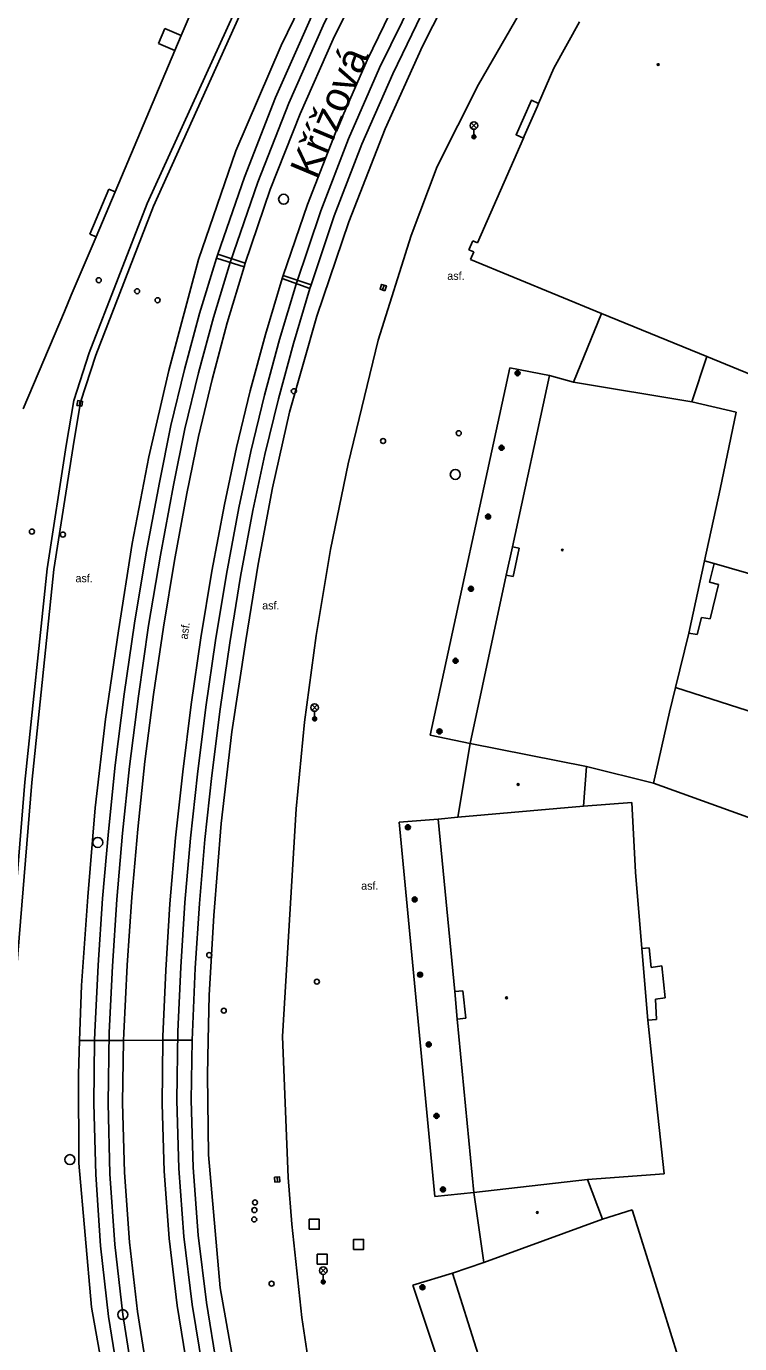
# Model space of a CAD drawing. Extents: x -599770 to -598493, y -1162076 to -1159209.
# Drawn here: x -599258.8 to -599223.2, y -1161450.6 to -1161384.7 of the extents above; entities that cross this region are included whole.
import ezdxf

# ---------------------------------------------------------------- set-up
doc = ezdxf.new("R2010")
doc.units = 0
doc.layers.add('Podklad', color=7, linetype='Continuous')

msp = doc.modelspace()

# ---------------------------------------------------------------- linework, layer by layer
at = {"layer": 'Podklad'}
for p, q in [((-599236.582, -1161389.83), (-599236.317, -1161389.565)), ((-599236.582, -1161389.565), (-599236.317, -1161389.83)), ((-599236.45, -1161389.885), (-599236.45, -1161390.26)), ((-599241.017, -1161397.919), (-599240.943, -1161397.681)), ((-599256.171, -1161403.713), (-599256.129, -1161403.467)), ((-599244.542, -1161418.93), (-599244.277, -1161418.665)), ((-599244.542, -1161418.665), (-599244.277, -1161418.93)), ((-599244.41, -1161418.985), (-599244.41, -1161419.36)), ((-599246.286, -1161442.265), (-599246.274, -1161442.515)), ((-599244.113, -1161447.08), (-599243.848, -1161446.815)), ((-599244.113, -1161446.815), (-599243.848, -1161447.08)), ((-599243.98, -1161447.135), (-599243.98, -1161447.51))]:
    msp.add_line(p, q, dxfattribs=at)
for points in [[(-599260.26, -1161446.97), (-599259.67, -1161436.44), (-599258.54, -1161422.55), (-599257.44, -1161411.89), (-599256.48, -1161405.74), (-599256.11, -1161403.52), (-599255.35, -1161401.18), (-599252.46, -1161393.72), (-599243.35, -1161373.53), (-599229.69, -1161346.19), (-599226.26, -1161338.15), (-599225.07, -1161333.53), (-599224.41, -1161329.22), (-599224.11, -1161321.1), (-599224.34, -1161312.95), (-599224.48, -1161311.25), (-599225.01, -1161307.91), (-599239.94, -1161263.56), (-599245.55, -1161247.67)], [(-599260.61, -1161447.02), (-599260.02, -1161436.42), (-599259.994, -1161436.099), (-599258.89, -1161422.52), (-599257.77, -1161411.86), (-599256.83, -1161405.69), (-599256.45, -1161403.44), (-599255.68, -1161401.06), (-599252.78, -1161393.59), (-599244.4, -1161375.21), (-599230.52, -1161347.14), (-599228.01, -1161341.44)], [(-599212.65, -1161353), (-599213.71, -1161354.36), (-599221.59, -1161366.91), (-599226.04, -1161372.65), (-599229.99, -1161377.9), (-599232.1, -1161380.86), (-599234.18, -1161384.1), (-599236.22, -1161387.65), (-599238.28, -1161391.75), (-599239.59, -1161395.19), (-599241.23, -1161400.43), (-599242.73, -1161406.61)], [(-599246.08, -1161385.69), (-599244.196, -1161381.806), (-599242.226, -1161377.966)], [(-599249.32, -1161396.32), (-599249.25, -1161396.12), (-599247.92, -1161392.28), (-599246.36, -1161388.3), (-599244.63, -1161384.39), (-599242.74, -1161380.56)], [(-599248.64, -1161396.54), (-599247.25, -1161392.53), (-599245.7, -1161388.58), (-599243.98, -1161384.7), (-599242.1, -1161380.89)], [(-599240.22, -1161478.52), (-599239.54, -1161478.26), (-599246.23, -1161460.82), (-599247.967, -1161454.377), (-599249.134, -1161447.807), (-599249.72, -1161441.16), (-599249.769, -1161437.168), (-599249.73, -1161435.43), (-599249.676, -1161433.176), (-599249.44, -1161429.19), (-599249.076, -1161424.592), (-599248.546, -1161420.01), (-599247.85, -1161415.45), (-599247.24, -1161411.621), (-599246.51, -1161407.813), (-599245.66, -1161404.03), (-599244.301, -1161399.231), (-599242.709, -1161394.504), (-599240.89, -1161389.86), (-599239.014, -1161385.727), (-599236.976, -1161381.672)], [(-599247.94, -1161396.76), (-599247.88, -1161396.58), (-599246.63, -1161392.9), (-599245.14, -1161389.11), (-599243.49, -1161385.38), (-599241.68, -1161381.73)], [(-599246.04, -1161397.35), (-599245.99, -1161397.19), (-599244.77, -1161393.65), (-599243.35, -1161390.01), (-599241.78, -1161386.43), (-599240.08, -1161382.91)], [(-599244.65, -1161397.84), (-599244.59, -1161397.66), (-599243.43, -1161394.21), (-599242.05, -1161390.63), (-599240.51, -1161387.11), (-599238.83, -1161383.67)], [(-599244.1, -1161393.96), (-599242.71, -1161390.36), (-599241.17, -1161386.81), (-599239.47, -1161383.34)], [(-599250.68, -1161384.26), (-599251.08, -1161385.2)], [(-599232.45, -1161386.83), (-599231.18, -1161384.51)], [(-599252.22, -1161385.6), (-599251.9, -1161384.85)], [(-599252.22, -1161385.6), (-599251.9, -1161384.85)], [(-599251.9, -1161384.85), (-599251.08, -1161385.2)], [(-599251.08, -1161385.2), (-599251.39, -1161385.95)], [(-599251.39, -1161385.95), (-599252.22, -1161385.6)], [(-599251.7, -1161401.95), (-599250.222, -1161396.399), (-599248.346, -1161390.969), (-599246.08, -1161385.69)], [(-599251.39, -1161385.95), (-599254.38, -1161393.01)], [(-599233.22, -1161388.59), (-599232.45, -1161386.83)], [(-599233.22, -1161388.59), (-599233.58, -1161388.43), (-599234.34, -1161390.16), (-599233.98, -1161390.32)], [(-599233.28, -1161388.73), (-599233.94, -1161390.23)], [(-599233.94, -1161390.23), (-599233.28, -1161388.73)], [(-599233.28, -1161388.73), (-599233.22, -1161388.59)], [(-599236.27, -1161395.56), (-599233.98, -1161390.32)], [(-599233.98, -1161390.32), (-599233.94, -1161390.23)], [(-599255.65, -1161395.12), (-599254.7, -1161392.88)], [(-599255.65, -1161395.12), (-599254.7, -1161392.88)], [(-599254.38, -1161393.01), (-599255.33, -1161395.26)], [(-599254.7, -1161392.88), (-599254.38, -1161393.01)], [(-599244.1, -1161393.96), (-599245.33, -1161397.63)], [(-599255.33, -1161395.26), (-599255.65, -1161395.12)], [(-599255.33, -1161395.26), (-599256.57, -1161398.18)], [(-599236.7, -1161395.91), (-599236.5, -1161395.46)], [(-599236.5, -1161395.46), (-599236.27, -1161395.56)], [(-599252.17, -1161407.54), (-599251.59, -1161404.7), (-599250.92, -1161401.89), (-599250.16, -1161399.09), (-599249.32, -1161396.32)], [(-599247.94, -1161396.76), (-599249.32, -1161396.32)], [(-599249.25, -1161396.12), (-599247.88, -1161396.58)], [(-599236.46, -1161396.01), (-599236.7, -1161395.91)], [(-599236.62, -1161396.4), (-599236.46, -1161396.01)], [(-599230.08, -1161399.1), (-599236.62, -1161396.4)], [(-599251.47, -1161407.67), (-599250.89, -1161404.86), (-599250.22, -1161402.06), (-599249.47, -1161399.29), (-599248.64, -1161396.54)], [(-599250.8, -1161408.1), (-599250.21, -1161405.24), (-599249.53, -1161402.39), (-599248.78, -1161399.56), (-599247.94, -1161396.76)], [(-599248.92, -1161408.64), (-599248.31, -1161405.79), (-599247.63, -1161402.96), (-599246.87, -1161400.14), (-599246.04, -1161397.35)], [(-599248.2, -1161408.81), (-599247.6, -1161405.99), (-599246.92, -1161403.18), (-599246.16, -1161400.39), (-599245.33, -1161397.63)], [(-599246.04, -1161397.35), (-599244.65, -1161397.84)], [(-599245.99, -1161397.19), (-599244.59, -1161397.66)], [(-599256.91, -1161398.99), (-599256.57, -1161398.18)], [(-599256.57, -1161398.18), (-599256.91, -1161398.99)], [(-599247.5, -1161408.95), (-599246.9, -1161406.14), (-599246.22, -1161403.36), (-599245.47, -1161400.59), (-599244.65, -1161397.84)], [(-599256.91, -1161398.99), (-599258.97, -1161403.86)], [(-599231.47, -1161402.53), (-599230.08, -1161399.1)], [(-599224.81, -1161401.24), (-599230.08, -1161399.1)], [(-599224.81, -1161401.24), (-599225.56, -1161403.51)], [(-599218.12, -1161403.99), (-599224.81, -1161401.24)], [(-599245.99, -1161479.47), (-599252.39, -1161462.85), (-599254.294, -1161455.88), (-599255.567, -1161448.768), (-599256.2, -1161441.57), (-599256.213, -1161437.129), (-599256.16, -1161435.44), (-599256.063, -1161432.69), (-599255.75, -1161428.26), (-599255.373, -1161423.812), (-599254.863, -1161419.377), (-599254.22, -1161414.96), (-599253.53, -1161410.595), (-599252.69, -1161406.257), (-599251.7, -1161401.95)], [(-599238.63, -1161420.17), (-599234.65, -1161401.81)], [(-599234.65, -1161401.81), (-599232.68, -1161402.2)], [(-599234.53, -1161410.76), (-599232.68, -1161402.2)], [(-599232.68, -1161402.2), (-599231.47, -1161402.53)], [(-599231.47, -1161402.53), (-599225.56, -1161403.51)], [(-599225.56, -1161403.51), (-599223.34, -1161404.02)], [(-599223.34, -1161404.02), (-599224.15, -1161407.88)], [(-599245.34, -1161423.86), (-599244.92, -1161419.52), (-599244.34, -1161415.19), (-599243.61, -1161410.89), (-599242.73, -1161406.61)], [(-599254.38, -1161421.67), (-599253.93, -1161418.12), (-599253.42, -1161414.58), (-599252.83, -1161411.06), (-599252.17, -1161407.54)], [(-599253.67, -1161421.75), (-599253.22, -1161418.22), (-599252.71, -1161414.69), (-599252.12, -1161411.18), (-599251.47, -1161407.68)], [(-599252.9, -1161421.5), (-599252.47, -1161418.14), (-599251.97, -1161414.78), (-599251.42, -1161411.44), (-599250.8, -1161408.1)], [(-599224.15, -1161407.88), (-599224.92, -1161411.46)], [(-599251, -1161422.01), (-599250.58, -1161418.65), (-599250.09, -1161415.31), (-599249.54, -1161411.97), (-599248.92, -1161408.64)], [(-599250.26, -1161422.12), (-599249.84, -1161418.78), (-599249.36, -1161415.44), (-599248.81, -1161412.12), (-599248.2, -1161408.81)], [(-599249.55, -1161422.2), (-599249.13, -1161418.87), (-599248.65, -1161415.56), (-599248.11, -1161412.25), (-599247.5, -1161408.95)], [(-599234.84, -1161412.18), (-599234.53, -1161410.76)], [(-599234.19, -1161410.83), (-599234.53, -1161410.76)], [(-599234.19, -1161410.83), (-599234.49, -1161412.25)], [(-599234.49, -1161412.25), (-599234.19, -1161410.83)], [(-599224.92, -1161411.46), (-599225.71, -1161415.08)], [(-599224.92, -1161411.46), (-599224.45, -1161411.6)], [(-599224.45, -1161411.6), (-599224.67, -1161412.53)], [(-599224.45, -1161411.6), (-599218.09, -1161413.43)], [(-599236.64, -1161420.6), (-599234.84, -1161412.18)], [(-599234.84, -1161412.18), (-599234.49, -1161412.25)], [(-599224.67, -1161412.53), (-599224.22, -1161412.64)], [(-599224.22, -1161412.64), (-599224.64, -1161414.36)], [(-599225.07, -1161414.29), (-599225.3, -1161415.15)], [(-599224.64, -1161414.36), (-599225.07, -1161414.29)], [(-599225.71, -1161415.08), (-599226.37, -1161417.8), (-599226.67, -1161419.03)], [(-599225.3, -1161415.15), (-599225.71, -1161415.08)], [(-599226.37, -1161417.8), (-599217.87, -1161420.52)], [(-599226.67, -1161419.03), (-599227.47, -1161422.58)], [(-599236.64, -1161420.6), (-599238.63, -1161420.17)], [(-599237.26, -1161424.28), (-599236.64, -1161420.6)], [(-599230.82, -1161421.75), (-599236.64, -1161420.6)], [(-599255.4, -1161435.02), (-599255.23, -1161431.68), (-599255.01, -1161428.34), (-599254.72, -1161425), (-599254.38, -1161421.67)], [(-599254.68, -1161435.05), (-599254.52, -1161431.72), (-599254.29, -1161428.39), (-599254.01, -1161425.07), (-599253.67, -1161421.75)], [(-599253.95, -1161435.07), (-599253.78, -1161431.67), (-599253.55, -1161428.28), (-599253.25, -1161424.88), (-599252.9, -1161421.5)], [(-599251.99, -1161435.24), (-599251.85, -1161431.92), (-599251.64, -1161428.61), (-599251.36, -1161425.31), (-599251, -1161422.01)], [(-599250.89, -1161428.55), (-599250.61, -1161425.33), (-599250.26, -1161422.12)], [(-599230.82, -1161421.75), (-599230.98, -1161423.72)], [(-599227.47, -1161422.58), (-599230.82, -1161421.75)], [(-599250.52, -1161435.03), (-599250.38, -1161431.82), (-599250.17, -1161428.6), (-599249.9, -1161425.4), (-599249.55, -1161422.2)], [(-599227.47, -1161422.58), (-599201.08, -1161432.1)], [(-599245.34, -1161423.86), (-599246.01, -1161435.25)], [(-599237.26, -1161424.28), (-599230.98, -1161423.72)], [(-599230.98, -1161423.72), (-599228.55, -1161423.55)], [(-599228.55, -1161423.55), (-599228.38, -1161427.03)], [(-599240.19, -1161424.53), (-599238.24, -1161424.37)], [(-599238.41, -1161443.24), (-599240.19, -1161424.53)], [(-599238.24, -1161424.37), (-599237.26, -1161424.28)], [(-599237.41, -1161433), (-599238.24, -1161424.37)], [(-599228.38, -1161427.03), (-599228.05, -1161430.85)], [(-599251.24, -1161435), (-599251.1, -1161431.78), (-599250.89, -1161428.55)], [(-599228.05, -1161430.85), (-599227.7, -1161430.81)], [(-599228.05, -1161430.85), (-599227.75, -1161434.43)], [(-599227.7, -1161430.81), (-599227.59, -1161431.8)], [(-599227.59, -1161431.8), (-599227.06, -1161431.71)], [(-599227.06, -1161431.71), (-599226.9, -1161433.31)], [(-599237.41, -1161433), (-599237, -1161432.96)], [(-599237.28, -1161434.37), (-599237.41, -1161433)], [(-599237, -1161432.96), (-599236.86, -1161434.33)], [(-599237, -1161432.96), (-599236.86, -1161434.33)], [(-599226.9, -1161433.31), (-599227.38, -1161433.38)], [(-599227.38, -1161433.38), (-599227.32, -1161434.39)], [(-599236.86, -1161434.33), (-599237.28, -1161434.37)], [(-599236.45, -1161443.05), (-599237.28, -1161434.37)], [(-599227.32, -1161434.39), (-599227.75, -1161434.43)], [(-599227.75, -1161434.43), (-599227.32, -1161438.56)], [(-599254.71, -1161449.25), (-599255.11, -1161445.71), (-599255.35, -1161442.15), (-599255.45, -1161438.59), (-599255.406, -1161435.436), (-599255.4, -1161435.02)], [(-599254, -1161449.15), (-599254.39, -1161445.64), (-599254.64, -1161442.11), (-599254.73, -1161438.58), (-599254.68, -1161435.05)], [(-599253.27, -1161448.99), (-599253.67, -1161445.52), (-599253.91, -1161442.04), (-599254.01, -1161438.56), (-599253.956, -1161435.435), (-599253.95, -1161435.07)], [(-599251.28, -1161448.69), (-599251.68, -1161445.34), (-599251.93, -1161441.98), (-599252.03, -1161438.61), (-599251.992, -1161435.432), (-599251.99, -1161435.24)], [(-599250.53, -1161448.64), (-599250.94, -1161445.25), (-599251.19, -1161441.84), (-599251.29, -1161438.42), (-599251.24, -1161435)], [(-599249.82, -1161448.54), (-599250.23, -1161445.18), (-599250.48, -1161441.8), (-599250.58, -1161438.42), (-599250.527, -1161435.431), (-599250.52, -1161435.03)], [(-599246.01, -1161435.25), (-599245.74, -1161442.29), (-599245.55, -1161444.63), (-599245.05, -1161449.3), (-599244.35, -1161453.95), (-599243.44, -1161458.33), (-599242.25, -1161462.63), (-599240.77, -1161466.85), (-599239.53, -1161469.74), (-599239.01, -1161470.96)], [(-599250.527, -1161435.431), (-599251.992, -1161435.432), (-599253.956, -1161435.435), (-599255.406, -1161435.436), (-599255.92, -1161435.437), (-599256.16, -1161435.437)], [(-599227.32, -1161438.56), (-599226.95, -1161442.11)], [(-599236.45, -1161443.05), (-599230.77, -1161442.39)], [(-599226.95, -1161442.11), (-599230.77, -1161442.39)], [(-599230.02, -1161444.38), (-599230.77, -1161442.39)], [(-599236.45, -1161443.05), (-599238.41, -1161443.24)], [(-599235.95, -1161446.54), (-599236.45, -1161443.05)], [(-599235.95, -1161446.54), (-599230.02, -1161444.38)], [(-599230.02, -1161444.38), (-599228.54, -1161443.91)], [(-599228.54, -1161443.91), (-599227.39, -1161447.57)], [(-599239.5, -1161447.67), (-599237.52, -1161447.07)], [(-599237.52, -1161447.07), (-599235.95, -1161446.54)], [(-599234.95, -1161455.21), (-599237.52, -1161447.07)], [(-599233.42, -1161465.94), (-599239.5, -1161447.67)], [(-599227.39, -1161447.57), (-599226.24, -1161451.28)], [(-599250.26, -1161462.26), (-599250.31, -1161462.1), (-599251.22, -1161458.99), (-599252.05, -1161455.69), (-599252.73, -1161452.35), (-599253.27, -1161448.99)], [(-599248.29, -1161461.64), (-599248.36, -1161461.42), (-599249.24, -1161458.45), (-599250.06, -1161455.23), (-599250.74, -1161451.97), (-599251.28, -1161448.69)], [(-599247.58, -1161461.45), (-599248.52, -1161458.29), (-599249.32, -1161455.11), (-599249.99, -1161451.89), (-599250.53, -1161448.64)], [(-599246.9, -1161461.21), (-599246.96, -1161461.01), (-599247.83, -1161458.09), (-599248.63, -1161454.94), (-599249.29, -1161451.75), (-599249.82, -1161448.54)], [(-599251.66, -1161462.69), (-599251.71, -1161462.52), (-599252.64, -1161459.38), (-599253.48, -1161456.04), (-599254.17, -1161452.66), (-599254.71, -1161449.25)], [(-599251.95, -1161459.18), (-599252.78, -1161455.87), (-599253.46, -1161452.52), (-599254, -1161449.15)]]:
    msp.add_lwpolyline(points, dxfattribs=at)
for points in [[(-599240.898, -1161397.957), (-599240.823, -1161397.718), (-599241.062, -1161397.643), (-599241.137, -1161397.882)], [(-599256.048, -1161403.734), (-599256.006, -1161403.488), (-599256.252, -1161403.446), (-599256.294, -1161403.692)], [(-599246.411, -1161442.272), (-599246.398, -1161442.521), (-599246.149, -1161442.508), (-599246.162, -1161442.259)], [(-599244.68, -1161444.88), (-599244.18, -1161444.88), (-599244.18, -1161444.38), (-599244.68, -1161444.38)], [(-599242.46, -1161445.89), (-599241.96, -1161445.89), (-599241.96, -1161445.39), (-599242.46, -1161445.39)], [(-599244.28, -1161446.63), (-599243.78, -1161446.63), (-599243.78, -1161446.13), (-599244.28, -1161446.13)]]:
    msp.add_lwpolyline(points, close=True, dxfattribs=at)
for centre, radius in [((-599227.24, -1161386.65), 0.045), ((-599227.24, -1161386.65), 0.0199), ((-599236.45, -1161389.698), 0.188), ((-599236.45, -1161390.26), 0.1), ((-599236.45, -1161390.26), 0.0723), ((-599236.45, -1161390.26), 0.0438), ((-599245.96, -1161393.38), 0.25), ((-599255.2, -1161397.43), 0.125), ((-599253.28, -1161397.98), 0.125), ((-599252.26, -1161398.43), 0.125), ((-599234.27, -1161402.08), 0.125), ((-599234.27, -1161402.08), 0.1), ((-599234.27, -1161402.08), 0.075), ((-599234.27, -1161402.08), 0.05), ((-599234.27, -1161402.08), 0.025), ((-599245.45, -1161402.98), 0.125), ((-599237.21, -1161405.08), 0.125), ((-599240.99, -1161405.47), 0.125), ((-599235.07, -1161405.81), 0.125), ((-599235.07, -1161405.81), 0.1), ((-599235.07, -1161405.81), 0.075), ((-599235.07, -1161405.81), 0.05), ((-599235.07, -1161405.81), 0.025), ((-599237.38, -1161407.14), 0.25), ((-599235.74, -1161409.25), 0.125), ((-599235.74, -1161409.25), 0.1), ((-599235.74, -1161409.25), 0.075), ((-599235.74, -1161409.25), 0.05), ((-599235.74, -1161409.25), 0.025), ((-599258.54, -1161410), 0.125), ((-599256.99, -1161410.15), 0.125), ((-599232.03, -1161410.92), 0.045), ((-599232.03, -1161410.92), 0.0199), ((-599236.6, -1161412.86), 0.125), ((-599236.6, -1161412.86), 0.1), ((-599236.6, -1161412.86), 0.075), ((-599236.6, -1161412.86), 0.05), ((-599236.6, -1161412.86), 0.025), ((-599237.37, -1161416.46), 0.125), ((-599237.37, -1161416.46), 0.1), ((-599237.37, -1161416.46), 0.075), ((-599237.37, -1161416.46), 0.05), ((-599237.37, -1161416.46), 0.025), ((-599244.41, -1161418.797), 0.188), ((-599244.41, -1161419.36), 0.1), ((-599244.41, -1161419.36), 0.0723), ((-599244.41, -1161419.36), 0.0438), ((-599238.17, -1161419.99), 0.125), ((-599238.17, -1161419.99), 0.1), ((-599238.17, -1161419.99), 0.075), ((-599238.17, -1161419.99), 0.05), ((-599238.17, -1161419.99), 0.025), ((-599234.24, -1161422.64), 0.045), ((-599234.24, -1161422.64), 0.0199), ((-599239.75, -1161424.78), 0.125), ((-599239.75, -1161424.78), 0.1), ((-599239.75, -1161424.78), 0.075), ((-599239.75, -1161424.78), 0.05), ((-599239.75, -1161424.78), 0.025), ((-599255.25, -1161425.54), 0.25), ((-599239.41, -1161428.39), 0.125), ((-599239.41, -1161428.39), 0.1), ((-599239.41, -1161428.39), 0.075), ((-599239.41, -1161428.39), 0.05), ((-599239.41, -1161428.39), 0.025), ((-599249.68, -1161431.17), 0.125), ((-599244.3, -1161432.5), 0.125), ((-599239.14, -1161432.15), 0.125), ((-599239.14, -1161432.15), 0.1), ((-599239.14, -1161432.15), 0.075), ((-599239.14, -1161432.15), 0.05), ((-599239.14, -1161432.15), 0.025), ((-599234.82, -1161433.31), 0.045), ((-599234.82, -1161433.31), 0.0199), ((-599248.95, -1161433.95), 0.125), ((-599238.71, -1161435.64), 0.125), ((-599238.71, -1161435.64), 0.1), ((-599238.71, -1161435.64), 0.075), ((-599238.71, -1161435.64), 0.05), ((-599238.71, -1161435.64), 0.025), ((-599238.32, -1161439.21), 0.125), ((-599238.32, -1161439.21), 0.1), ((-599238.32, -1161439.21), 0.075), ((-599238.32, -1161439.21), 0.05), ((-599238.32, -1161439.21), 0.025), ((-599256.64, -1161441.4), 0.25), ((-599238, -1161442.89), 0.125), ((-599238, -1161442.89), 0.1), ((-599238, -1161442.89), 0.075), ((-599238, -1161442.89), 0.05), ((-599238, -1161442.89), 0.025), ((-599247.42, -1161443.92), 0.125), ((-599247.39, -1161443.54), 0.125), ((-599247.43, -1161444.39), 0.125), ((-599233.28, -1161444.04), 0.045), ((-599233.28, -1161444.04), 0.0199), ((-599243.98, -1161446.948), 0.188), ((-599246.56, -1161447.6), 0.125), ((-599243.98, -1161447.51), 0.1), ((-599243.98, -1161447.51), 0.0723), ((-599243.98, -1161447.51), 0.0438), ((-599239.02, -1161447.78), 0.125), ((-599239.02, -1161447.78), 0.1), ((-599239.02, -1161447.78), 0.075), ((-599239.02, -1161447.78), 0.05), ((-599239.02, -1161447.78), 0.025), ((-599254, -1161449.15), 0.25)]:
    msp.add_circle(centre, radius, dxfattribs=at)

# ---------------------------------------------------------------- texts
for s, height, rotation, p in [('Křížová', 1.5, 67.25, (-599244.3, -1161392.45)), ('asf.', 0.4, 81.43, (-599250.77, -1161415.41))]:
    msp.add_text(s, height=height, rotation=rotation, dxfattribs=at).set_placement(p)
for p in [(-599237.78, -1161397.413), (-599256.36, -1161412.53), (-599247.03, -1161413.89), (-599242.084, -1161427.904)]:
    msp.add_text('asf.', height=0.4, dxfattribs=at).set_placement(p)

doc.saveas('drawing.dxf')
